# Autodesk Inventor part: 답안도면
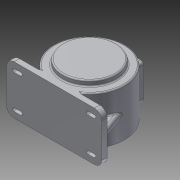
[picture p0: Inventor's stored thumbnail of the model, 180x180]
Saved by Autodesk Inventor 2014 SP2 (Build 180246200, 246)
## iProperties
Created: 2015-06
Part Number: 답안도면
Material: 알루미늄 6061
Document SubType Name: Sheet Metal
Designer: 201-01
Mass: 3403.94 g
Surface Area: 2279.14 cm^2
Volume: 1256.07 cm^3
Density: 2.71 g/cm^3
Sheet Metal Rule: Default_mm
Appearance: 알루미늄 - 평지
Author: 201-01
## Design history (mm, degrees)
sketch "스케치1"
  geometry: L1 (-97, 59)-(97, 59); L2 (115, 41)-(115, -41); L3 (97, -59)-(-97, -59); L4 (-115, -41)-(-115, 41); A1 r 18 centre (97, -41) between (97, -59) and (115, -41); A2 r 18 centre (97, 41) between (115, 41) and (97, 59); A3 r 18 centre (-97, 41) between (-97, 59) and (-115, 41); A4 r 18 centre (-97, -41) between (-115, -41) and (-97, -59); 4 further points
  constraints: 8 end point, 8 point on circle, 8 tangent, 6 point on line, 4 centre point, 3 equal radius, 2 parallel, 1 horizontal, 1 perpendicular
  dimensions: "d0" = 230 distance of point (115, -59) point (-115, -59); "d1" = 118 distance of point (-115, -59) point (-115, 59); "d2" = 115 horizontal distance of point (0, 0) point (-115, 59); "d4" = 59 vertical distance of point (0, 0) point (115, -59); "d5" = 18 radius of A1
extrude "돌출1" join sketch "스케치1" distance "d6" = 13; taper "d7" = 0 deg
sketch "스케치2"
  geometry: L1 (-115, 41)-(-115, -41) reference; L2 (-97, -59)-(97, -59) reference; L3 (115, -41)-(115, 41) reference; L4 (97, 59)-(-97, 59) reference; L5 (0, 59)-(0, 41); L6 (0, 41)-(97, 41); L7 (97, 41)-(81, 41); L8 (81, 50)-(97, 50); L9 (81, 32)-(97, 32); L10 (-115, 0)-(115, 0); L11 (81, -32)-(97, -32); L12 (81, -50)-(97, -50); L13 (-81, 32)-(-97, 32); L14 (-81, 50)-(-97, 50); L15 (-81, -32)-(-97, -32); L16 (-81, -50)-(-97, -50); A1 r 18 centre (-97, -41) between (-115, -41) and (-97, -59) reference; A2 r 18 centre (97, -41) between (97, -59) and (115, -41) reference; A3 r 18 centre (97, 41) between (115, 41) and (97, 59) reference; A4 r 18 centre (-97, 41) between (-97, 59) and (-115, 41) reference; A5 r 9 centre (97, 41) between (97, 32) and (97, 50); A6 r 9 centre (81, 41) between (81, 50) and (81, 32); A7 r 9 centre (97, -41) between (97, -50) and (97, -32); A8 r 9 centre (81, -41) between (81, -32) and (81, -50); A9 r 9 centre (-97, 41) between (-97, 50) and (-97, 32); A10 r 9 centre (-81, 41) between (-81, 32) and (-81, 50); A11 r 9 centre (-97, -41) between (-97, -32) and (-97, -50); A12 r 9 centre (-81, -41) between (-81, -50) and (-81, -32); 2 further points
  constraints: 24 end point, 19 symmetric about line, 16 point on circle, 8 centre point, 3 midpoint, 2 coincident, 2 tangent, 1 parallel, 1 perpendicular, 1 point on line, 6 other
  dimensions: "d9" = 18 distance of L5.start L5.end; "d11" = 16 distance of L6.end L7.end
extrude "돌출2" join sketch "스케치2" distance "d22" = 3; taper "d23" = 0 deg
sketch "스케치3"
  geometry: L1 (-97, 32)-(-81, 32) reference; L2 (-81, 50)-(-97, 50) reference; L3 (-97, 45)-(-81, 45); L4 (-81, 37)-(-97, 37); L5 (0, 0)-(0, 37); L6 (0, 0)-(-32.171, 0); L7 (97, 45)-(81, 45); L8 (81, 37)-(97, 37); L9 (-97, -45)-(-81, -45); L10 (-81, -37)-(-97, -37); L11 (97, -45)-(81, -45); L12 (81, -37)-(97, -37); A1 r 9 centre (-81, 41) between (-81, 32) and (-81, 50) reference; A2 r 9 centre (-97, 41) between (-97, 50) and (-97, 32) reference; A3 r 4 centre (-81, 41) between (-81, 37) and (-81, 45); A4 r 4 centre (-97, 41) between (-97, 45) and (-97, 37); A5 r 4 centre (81, 41) between (81, 45) and (81, 37); A6 r 4 centre (97, 41) between (97, 37) and (97, 45); A7 r 4 centre (-81, -41) between (-81, -45) and (-81, -37); A8 r 4 centre (-97, -41) between (-97, -37) and (-97, -45); A9 r 4 centre (81, -41) between (81, -37) and (81, -45); A10 r 4 centre (97, -41) between (97, -45) and (97, -37)
  constraints: 20 end point, 18 symmetric about line, 16 point on circle, 8 centre point, 2 perpendicular, 9 other
  dimensions: "d24" = 8 distance between parallel lines of L4 L3
extrude "돌출3" cut sketch "스케치3" stored distance "d25" = 3; taper "d26" = 0 deg
fillet "모깎기1" dims "d27" = 4
sketch "스케치5"
  geometry: L1 (0, 0)-(0, 85); C1 r 85 at (0, 85)
  constraints: 2 end point, 1 centre point, 1 coincident, 1 vertical
  dimensions: "d28" = 85 distance of L1.start L1.end; "d29" = 170 diameter of C1
extrude "돌출4" join sketch "스케치5" stored distance "d30" = 118; taper "d31" = 0 deg
sketch "스케치6"
  geometry: L1 (-97, 0)-(97, 0) reference; L2 (97, 0)-(97, 13) reference; L3 (45.177, 13)-(97, 13) reference; L4 (-97, 13)-(-45.177, 13) reference; L5 (-97, 0)-(-97, 13) reference; C1 r 77 at (0, 85); A1 r 85 centre (0, 85) between (45.177, 13) and (-45.177, 13) reference; 1 further point
  constraints: 1 centre point, 1 coincident
  dimensions: "d32" = 154 diameter of C1
extrude "돌출5" cut sketch "스케치6" distance "d33" = 47.5; taper "d34" = 0 deg; dims "d43" = 51, "d44" = 0
sketch "스케치7"
  geometry: L1 (0, 0)-(194, 0) reference; L2 (194, 0)-(194, 13) reference; L3 (142.177, 13)-(194, 13) reference; L4 (0, 13)-(51.823, 13) reference; L5 (0, 0)-(0, 13) reference; C1 r 47.5 at (97, 85); A1 r 85 centre (97, 85) between (142.177, 13) and (51.823, 13) reference; 1 further point
  constraints: 1 centre point, 1 coincident
  dimensions: "d35" = 95 diameter of C1
extrude "돌출6" cut sketch "스케치7" distance "d36" = 11; taper "d37" = 0 deg
fillet "모깎기2" dims "d41" = 3
fillet "모깎기3" dims "d42" = 3
sketch "스케치8"
  geometry: C1 r 74 at (0, 0) reference; C2 r 23.5 at (0, 0); 1 further point
  constraints: 1 centre point, 1 coincident
  dimensions: "d45" = 47 diameter of C2
extrude "돌출7" cut sketch "스케치8" distance "d46" = 14; taper "d47" = 0 deg
sketch "스케치9"
  geometry: L1 (0, 0)-(194, 0) reference; L2 (194, 0)-(194, 13) reference; L3 (142.177, 13)-(194, 13) reference; L4 (0, 13)-(51.823, 13) reference; L5 (0, 0)-(0, 13) reference; C1 r 23.5 at (97, 85) reference; C2 r 65 at (97, 85); A1 r 85 centre (97, 85) between (142.177, 13) and (51.823, 13) reference; 1 further point
  constraints: 1 centre point, 1 coincident
  dimensions: "d48" = 130 diameter of C2
extrude "돌출8" join sketch "스케치9" distance "d49" = 13; taper "d50" = 0 deg
fillet "모깎기4" dims "d51" = 3
sketch "스케치10"
  geometry: C1 r 23.5 at (0, 0) reference; C2 r 15 at (0, 0); 1 further point
  constraints: 1 centre point, 1 coincident
  dimensions: "d52" = 30 diameter of C2
extrude "돌출9" cut sketch "스케치10" distance "d53" = 3; taper "d54" = 0 deg
fillet "모깎기5" dims "d55" = 3
node "작업 평면1"
sketch "스케치13"
  geometry: C1 r 65 at (97, 85); C2 r 47.5 at (97, 85) reference; 1 further point
  constraints: 1 centre point
  dimensions: "d67" = 130 diameter of C1
extrude "돌출12" join sketch "스케치13" distance "d68" = 3; taper "d69" = 0 deg
chamfer "모따기3" distance "d70" = 1; stored, may be unused: second distance "d71" = 2, angle "d72" = 45 deg
fillet "모깎기7" dims "d73" = 3
sketch "스케치14" dims "d74" = 12
  geometry: L1 (97, 0)-(115, 0) reference; L2 (115, 0)-(115, 13) reference; L3 (97, 13)-(115, 13) reference; L4 (97, 0)-(97, 13) reference; L5 (109, 13)-(84.818, 79.44); L6 (97, 13)-(39.243, 13) reference; L7 (115, 13)-(97, 13) reference; L8 (109, 13)-(45.177, 13); A1 r 85 centre (0, 85) between (45.177, 13) and (-45.177, 13) reference; 2 further points
  constraints: 4 end point, 1 coincident, 1 horizontal alignment, 1 point on circle, 1 point on line, 2 other
  node "투영된 루프9"
sketch "스케치15"
  geometry: L1 (-35.5, 42.5)-(35.5, 42.5); L2 (42.5, 35.5)-(42.5, -35.5); L3 (35.5, -42.5)-(-35.5, -42.5); L4 (-42.5, -35.5)-(-42.5, 35.5); A1 r 7 centre (-35.5, 35.5) between (-35.5, 42.5) and (-42.5, 35.5); A2 r 7 centre (-35.5, -35.5) between (-42.5, -35.5) and (-35.5, -42.5); A3 r 7 centre (35.5, -35.5) between (35.5, -42.5) and (42.5, -35.5); A4 r 7 centre (35.5, 35.5) between (42.5, 35.5) and (35.5, 42.5); 4 further points
  constraints: 8 end point, 8 point on circle, 8 tangent, 6 point on line, 4 centre point, 3 equal radius, 2 parallel, 1 horizontal, 1 perpendicular
  dimensions: "d84" = 85 distance of point (-42.5, 42.5) point (42.5, 42.5); "d85" = 85 distance of point (-42.5, -42.5) point (-42.5, 42.5); "d86" = 42.5 horizontal distance of point (-42.5, 42.5) point (0, 0); "d87" = 42.5 horizontal distance of point (0, 0) point (42.5, 42.5); "d88" = 7 radius of A1
extrude "돌출13" join sketch "스케치15" stored distance "d89" = 3; taper "d90" = 0 deg
sketch "스케치16"
  geometry: C1 r 35 at (0, 0); 1 further point
  constraints: 1 centre point, 1 coincident
  dimensions: "d91" = 70 diameter of C1
extrude "돌출14" cut sketch "스케치16" stored distance "d92" = 3; taper "d93" = 0 deg
chamfer "모따기4" distance "d94" = 1; stored, may be unused: second distance "d95" = 2, angle "d96" = 45 deg
fillet "모깎기9" dims "d97" = 3
extrude "돌출15" join sketch "스케치14" stored distance "d98" = 15; taper "d99" = 0 deg
fillet "모깎기10" dims "d100" = 7.5
fillet "모깎기11" dims "d101" = 3
fillet "모깎기12" dims "d102" = 3
hole "구멍1" diameter "d105" = 3.242; stored, may be unused: countersink angle "d109" = 90 deg, drill point angle "d111" = 118 deg; dims "d103" = 10, "d104" = 10, "d106" = 10, "d107" = 4, "d108" = 2, "d110" = 13
hole "구멍2" diameter "d114" = 3.242; stored, may be unused: countersink angle "d118" = 90 deg, drill point angle "d120" = 118 deg; dims "d112" = 10, "d113" = 10, "d115" = 10, "d116" = 4, "d117" = 2, "d119" = 13
hole "구멍3" diameter "d123" = 3.242; stored, may be unused: countersink angle "d127" = 90 deg, drill point angle "d129" = 118 deg; dims "d121" = 10, "d122" = 10, "d124" = 10, "d125" = 4, "d126" = 2, "d128" = 13
hole "구멍4" diameter "d132" = 3.242; stored, may be unused: countersink angle "d136" = 90 deg, drill point angle "d138" = 118 deg; dims "d130" = 10, "d131" = 10, "d133" = 10, "d134" = 4, "d135" = 2, "d137" = 13
sketch "스케치17"
  geometry: L1 (0, 0)-(194, 0) reference; L2 (97, 85)-(174.036, 120.923); A1 r 85 centre (97, 85) between (149.755, 18.352) and (44.245, 18.352) reference; 2 further points
  constraints: 2 end point, 1 coincident, 1 point on circle
  dimensions: "d140" = 25 deg angle of L1 L2
node "작업 평면2"
sketch "스케치18"
  geometry: L1 (-7.329, 19.37)-(-7.329, 98.196); L2 (-7.329, 98.196)-(8.671, 98.196); L3 (8.671, 98.196)-(8.671, 19.37); L4 (8.671, 19.37)-(-7.329, 19.37); L5 (81.26, 0)-(-82, 0) reference; L6 (39.453, 66.5)-(-12.282, 66.5) reference; 2 further points
  constraints: 2 other
feature "엠보싱1" sketch "스케치18" dims "d144" = 0.5, "d145" = 0
node "솔리드1"
mirror "대칭1"
node "투영된 루프1"
node "투영된 루프2"
node "투영된 루프3"
node "투영된 루프4"
node "투영된 루프5"
node "투영된 루프6"
node "투영된 루프7"
other parameters: "SeamGap" = 0.01, "d20" = 18, "d21" = 18, "d56" = 173, "d76" = 110 deg
